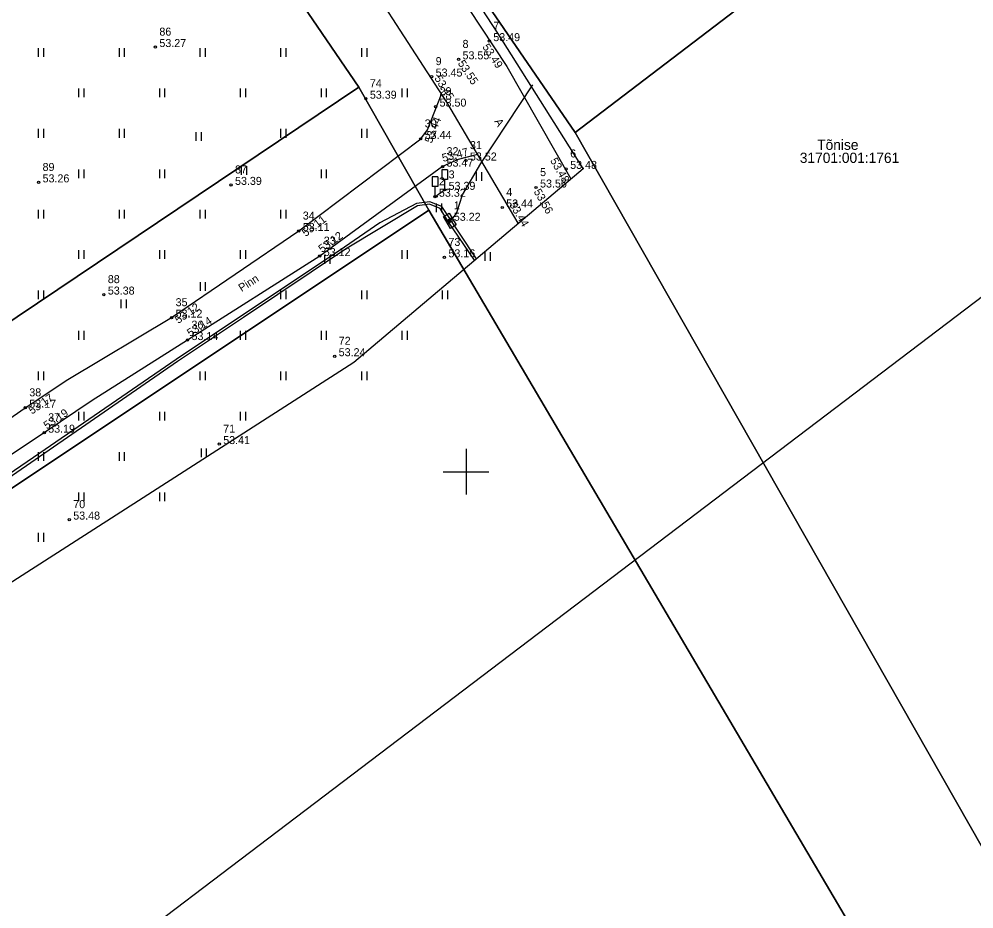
# Model space of a CAD drawing. Extents: x 538599 to 541973, y 6559689 to 6564516.
# Drawn here: x 540610.9 to 540694.4, y 6561211.7 to 6561289.6 of the extents above; entities that cross this region are included whole.
import ezdxf

# ---------------------------------------------------------------- set-up
doc = ezdxf.new("R2010")
doc.units = 0
for name, color, linetype in [('ELRAJATISMP', 7, 'Continuous'), ('HALJASTUS', 7, 'Continuous'), ('KORGUS-EH2000', 7, 'Continuous'), ('KPKAABEL', 7, 'Continuous'), ('LIIKLUS', 7, 'Continuous'), ('MOOTKORG-EH2000', 7, 'Continuous'), ('MOOTMPUNKT', 7, 'Continuous'), ('MOOTNR', 7, 'Continuous'), ('MOOTPIIR', 7, 'Continuous'), ('MPKAABEL', 7, 'Continuous'), ('PIIR', 7, 'Continuous'), ('TEE', 7, 'Continuous'), ('VORK', 7, 'Continuous'), ('VORMISTUS', 7, 'Continuous')]:
    doc.layers.add(name, color=color, linetype=linetype)

msp = doc.modelspace()

# ---------------------------------------------------------------- linework, layer by layer
at = {"layer": 'ELRAJATISMP'}
for p, q in [((540648.769, 6561272.238), (540648.255, 6561271.934)), ((540648.907, 6561272.004), (540648.393, 6561271.7))]:
    msp.add_line(p, q, dxfattribs=at)
msp.add_lwpolyline([(540648.534, 6561272.635), (540649.142, 6561271.607), (540648.628, 6561271.303), (540648.02, 6561272.331)], close=True, dxfattribs=at)
at = {"layer": 'HALJASTUS'}
for p, q in [((540612.567, 6561287.072), (540612.567, 6561286.31)), ((540613.022, 6561287.072), (540613.022, 6561286.31)), ((540619.638, 6561287.072), (540619.638, 6561286.31)), ((540620.093, 6561287.072), (540620.093, 6561286.31)), ((540626.709, 6561287.072), (540626.709, 6561286.31)), ((540627.164, 6561287.072), (540627.164, 6561286.31)), ((540633.78, 6561287.072), (540633.78, 6561286.31)), ((540634.235, 6561287.072), (540634.235, 6561286.31)), ((540640.851, 6561287.072), (540640.851, 6561286.31)), ((540641.307, 6561287.072), (540641.307, 6561286.31)), ((540616.103, 6561283.536), (540616.103, 6561282.775)), ((540616.558, 6561283.536), (540616.558, 6561282.775)), ((540623.174, 6561283.536), (540623.174, 6561282.775)), ((540623.629, 6561283.536), (540623.629, 6561282.775)), ((540630.245, 6561283.536), (540630.245, 6561282.775)), ((540630.7, 6561283.536), (540630.7, 6561282.775)), ((540637.316, 6561283.536), (540637.316, 6561282.775)), ((540637.771, 6561283.536), (540637.771, 6561282.775)), ((540644.387, 6561283.536), (540644.387, 6561282.775)), ((540644.842, 6561283.536), (540644.842, 6561282.775)), ((540612.567, 6561280), (540612.567, 6561279.239)), ((540613.022, 6561280), (540613.022, 6561279.239)), ((540619.638, 6561280), (540619.638, 6561279.239)), ((540620.093, 6561280), (540620.093, 6561279.239)), ((540626.363, 6561279.719), (540626.363, 6561278.958)), ((540626.818, 6561279.719), (540626.818, 6561278.958)), ((540633.78, 6561280), (540633.78, 6561279.239)), ((540634.235, 6561280), (540634.235, 6561279.239)), ((540640.851, 6561280), (540640.851, 6561279.239)), ((540641.307, 6561280), (540641.307, 6561279.239)), ((540616.103, 6561276.465), (540616.103, 6561275.704)), ((540616.558, 6561276.465), (540616.558, 6561275.704)), ((540623.174, 6561276.465), (540623.174, 6561275.704)), ((540623.629, 6561276.465), (540623.629, 6561275.704)), ((540630.328, 6561276.757), (540630.328, 6561275.996)), ((540630.783, 6561276.757), (540630.783, 6561275.996)), ((540637.316, 6561276.465), (540637.316, 6561275.704)), ((540637.771, 6561276.465), (540637.771, 6561275.704)), ((540650.899, 6561276.211), (540650.899, 6561275.45)), ((540651.354, 6561276.211), (540651.354, 6561275.45)), ((540647.4, 6561273.477), (540647.4, 6561272.716)), ((540647.855, 6561273.477), (540647.855, 6561272.716)), ((540612.567, 6561272.929), (540612.567, 6561272.168)), ((540613.022, 6561272.929), (540613.022, 6561272.168)), ((540619.638, 6561272.929), (540619.638, 6561272.168)), ((540620.093, 6561272.929), (540620.093, 6561272.168)), ((540626.709, 6561272.929), (540626.709, 6561272.168)), ((540627.164, 6561272.929), (540627.164, 6561272.168)), ((540633.78, 6561272.929), (540633.78, 6561272.168)), ((540634.235, 6561272.929), (540634.235, 6561272.168)), ((540616.103, 6561269.394), (540616.103, 6561268.633)), ((540616.558, 6561269.394), (540616.558, 6561268.633)), ((540623.174, 6561269.394), (540623.174, 6561268.633)), ((540623.629, 6561269.394), (540623.629, 6561268.633)), ((540630.245, 6561269.394), (540630.245, 6561268.633)), ((540630.7, 6561269.394), (540630.7, 6561268.633)), ((540637.627, 6561268.962), (540637.627, 6561268.201)), ((540638.082, 6561268.962), (540638.082, 6561268.201)), ((540644.387, 6561269.394), (540644.387, 6561268.633)), ((540644.842, 6561269.394), (540644.842, 6561268.633)), ((540651.644, 6561269.211), (540651.644, 6561268.45)), ((540652.099, 6561269.211), (540652.099, 6561268.45)), ((540626.726, 6561266.598), (540626.726, 6561265.837)), ((540627.181, 6561266.598), (540627.181, 6561265.837)), ((540612.567, 6561265.858), (540612.567, 6561265.097)), ((540613.022, 6561265.858), (540613.022, 6561265.097)), ((540633.78, 6561265.858), (540633.78, 6561265.097)), ((540634.235, 6561265.858), (540634.235, 6561265.097)), ((540640.851, 6561265.858), (540640.851, 6561265.097)), ((540641.307, 6561265.858), (540641.307, 6561265.097)), ((540647.923, 6561265.858), (540647.923, 6561265.097)), ((540648.378, 6561265.858), (540648.378, 6561265.097)), ((540619.805, 6561265.076), (540619.805, 6561264.315)), ((540620.26, 6561265.076), (540620.26, 6561264.315)), ((540616.103, 6561262.323), (540616.103, 6561261.562)), ((540616.558, 6561262.323), (540616.558, 6561261.562)), ((540630.245, 6561262.323), (540630.245, 6561261.562)), ((540630.7, 6561262.323), (540630.7, 6561261.562)), ((540637.316, 6561262.323), (540637.316, 6561261.562)), ((540637.771, 6561262.323), (540637.771, 6561261.562)), ((540644.387, 6561262.323), (540644.387, 6561261.562)), ((540644.842, 6561262.323), (540644.842, 6561261.562)), ((540612.567, 6561258.787), (540612.567, 6561258.026)), ((540613.022, 6561258.787), (540613.022, 6561258.026)), ((540626.709, 6561258.787), (540626.709, 6561258.026)), ((540627.164, 6561258.787), (540627.164, 6561258.026)), ((540633.78, 6561258.787), (540633.78, 6561258.026)), ((540634.235, 6561258.787), (540634.235, 6561258.026)), ((540640.851, 6561258.787), (540640.851, 6561258.026)), ((540641.307, 6561258.787), (540641.307, 6561258.026)), ((540616.103, 6561255.252), (540616.103, 6561254.491)), ((540616.558, 6561255.252), (540616.558, 6561254.491)), ((540623.174, 6561255.252), (540623.174, 6561254.491)), ((540623.629, 6561255.252), (540623.629, 6561254.491)), ((540630.245, 6561255.252), (540630.245, 6561254.491)), ((540630.7, 6561255.252), (540630.7, 6561254.491)), ((540612.567, 6561251.716), (540612.567, 6561250.955)), ((540613.022, 6561251.716), (540613.022, 6561250.955)), ((540619.638, 6561251.716), (540619.638, 6561250.955)), ((540620.093, 6561251.716), (540620.093, 6561250.955)), ((540626.82, 6561252.041), (540626.82, 6561251.28)), ((540627.275, 6561252.041), (540627.275, 6561251.28)), ((540616.103, 6561248.181), (540616.103, 6561247.42)), ((540616.558, 6561248.181), (540616.558, 6561247.42)), ((540623.174, 6561248.181), (540623.174, 6561247.42)), ((540623.629, 6561248.181), (540623.629, 6561247.42)), ((540612.567, 6561244.645), (540612.567, 6561243.884)), ((540613.022, 6561244.645), (540613.022, 6561243.884))]:
    msp.add_line(p, q, dxfattribs=at)
at = {"layer": 'KORGUS-EH2000'}
for centre in [(540622.82, 6561287.171), (540652.037, 6561287.689), (540649.345, 6561286.097), (540646.993, 6561284.59), (540641.235, 6561282.651), (540646.035, 6561279.138), (540647.947, 6561276.705), (540658.764, 6561276.507), (540612.599, 6561275.328), (540629.439, 6561275.108), (540656.13, 6561274.878), (540653.169, 6561273.131), (540635.368, 6561271.073), (540637.204, 6561268.881), (540648.112, 6561268.767), (540618.309, 6561265.51), (540624.24, 6561263.49), (540625.631, 6561261.527), (540638.509, 6561260.115), (540611.437, 6561255.604), (540613.091, 6561253.422), (540628.405, 6561252.425), (540615.285, 6561245.819)]:
    msp.add_circle(centre, 0.1, dxfattribs=at)
at = {"layer": 'KPKAABEL'}
msp.add_lwpolyline([(540650.91, 6561268.65), (540647.879, 6561273.223), (540646.82, 6561273.613), (540645.676, 6561273.469), (540642.461, 6561271.781), (540639.363, 6561269.658), (540624.625, 6561259.82), (540612.707, 6561251.641), (540589.754, 6561235.922)], dxfattribs=at)
at = {"layer": 'LIIKLUS'}
for p, q in [((540647.878, 6561276.425), (540647.878, 6561275.575)), ((540648.378, 6561276.425), (540647.878, 6561276.425)), ((540648.378, 6561276.425), (540648.378, 6561275.575)), ((540647.03, 6561275.82), (540647.03, 6561274.97)), ((540647.53, 6561275.82), (540647.03, 6561275.82)), ((540647.53, 6561275.82), (540647.53, 6561274.97)), ((540648.378, 6561275.575), (540647.878, 6561275.575)), ((540648.128, 6561275.575), (540648.128, 6561274.675)), ((540647.53, 6561274.97), (540647.03, 6561274.97)), ((540647.28, 6561274.97), (540647.28, 6561274.07)), ((540647.53, 6561274.07), (540647.28, 6561274.07)), ((540648.378, 6561274.675), (540648.128, 6561274.675))]:
    msp.add_line(p, q, dxfattribs=at)
msp.add_lwpolyline([(540647.28, 6561274.07), (540648.128, 6561274.675)], dxfattribs=at)
at = {"layer": 'MOOTMPUNKT'}
for centre in [(540622.82, 6561287.171), (540652.037, 6561287.689), (540649.345, 6561286.097), (540646.993, 6561284.59), (540641.235, 6561282.651), (540647.339, 6561281.959), (540646.035, 6561279.138), (540649.992, 6561277.241), (540647.947, 6561276.705), (540658.764, 6561276.507), (540612.599, 6561275.328), (540629.439, 6561275.108), (540648.128, 6561274.675), (540656.13, 6561274.878), (540647.28, 6561274.07), (540653.169, 6561273.131), (540648.581, 6561271.969), (540635.368, 6561271.073), (540637.204, 6561268.881), (540648.112, 6561268.767), (540618.309, 6561265.51), (540624.24, 6561263.49), (540625.631, 6561261.527), (540638.509, 6561260.115), (540611.437, 6561255.604), (540613.091, 6561253.422), (540628.405, 6561252.425), (540615.285, 6561245.819)]:
    msp.add_circle(centre, 0.1, dxfattribs=at)
at = {"layer": 'MOOTPIIR'}
msp.add_lwpolyline([(540582.869, 6561222.817), (540621.742, 6561247.747), (540640.195, 6561259.582), (540660.245, 6561276.551), (540652.795, 6561288.389), (540643.616, 6561302.458), (540615.416, 6561343.631), (540611.814, 6561347.628), (540600.551, 6561344.045)], dxfattribs=at)
at = {"layer": 'MPKAABEL'}
for points in [[(540648.449, 6561271.91), (540648.833, 6561272.204), (540649.157, 6561272.59), (540649.689, 6561274.252), (540651.306, 6561276.976), (540655.855, 6561283.862)], [(540650.747, 6561268.512), (540648.449, 6561271.91), (540647.738, 6561273.055), (540646.801, 6561273.41), (540645.746, 6561273.277), (540639.444, 6561269.471), (540630.539, 6561263.496), (540624.746, 6561259.652), (540607.46, 6561247.735)]]:
    msp.add_lwpolyline(points, dxfattribs=at)
at = {"layer": 'PIIR'}
for points in [[(540290.72, 6561746.68), (540427.24, 6561588.74), (540493.94, 6561511.13), (540543.58, 6561450.93), (540540.24, 6561448.03), (540578.89, 6561396.62), (540600.99, 6561365.08), (540659.54, 6561279.7), (540697.59, 6561212.89), (540728.6, 6561157.63), (540756.94, 6561107.21), (540762.6, 6561098.5), (540765.3, 6561101.59), (540815.83, 6561019.53), (540863.6, 6560935.22), (540880.61, 6560910.09), (540903.4, 6560875.14), (540927.11, 6560842.51), (540955.71, 6560805.99), (540982.2, 6560772.63), (541049.12, 6560693.03)], [(541045.65, 6560666.8), (540964.7, 6560765.19), (540868.94, 6560895.75), (540756.19, 6561084.56), (540744.95, 6561099.98), (540716.4, 6561150.76), (540687.02, 6561204.55), (540646.74, 6561272.89), (540640.63, 6561283.66), (540606.26, 6561333.96), (540569.6, 6561385.93), (540537.11, 6561431.06), (540500.82, 6561475.34), (540460.86, 6561522.64), (540423.13, 6561566.69), (540380.29, 6561616.49), (540342.1, 6561660.8)]]:
    msp.add_lwpolyline(points, dxfattribs=at)
for points in [[(540600.99, 6561365.08), (540701.8, 6561446.25), (540826.84, 6561548.44), (540828.67, 6561550.37), (540829.75, 6561549.48), (540833.57, 6561546.34), (540844.1, 6561537.92), (540853.65, 6561531.83), (540859.93, 6561522.78), (540863.38, 6561506.22), (540873.29, 6561464.28), (540881.92, 6561432.26), (540885.77, 6561408.65), (540892.47, 6561398.48), (540907.42, 6561381.68), (540938.49, 6561347.15), (540935.17, 6561343.58), (540808.31, 6561283.67), (540793.04, 6561301.15), (540771.58, 6561325.47), (540750.46, 6561349.5), (540705.14, 6561314.47), (540659.54, 6561279.7)], [(540491.21, 6561183.5), (540566.07, 6561233.36), (540528.84, 6561281.85), (540494.34, 6561324.62), (540458.27, 6561368.69), (540424.68, 6561408.57), (540384.55, 6561455.73), (540346.17, 6561499.11), (540330.12, 6561517.14), (540337.36, 6561523.32), (540348.28, 6561532.96), (540364.11, 6561514.94), (540353.14, 6561505.27), (540391.51, 6561461.86), (540431.74, 6561414.74), (540465.17, 6561374.89), (540501.31, 6561330.86), (540535.92, 6561287.97), (540573.77, 6561238.75), (540640.63, 6561283.66), (540646.74, 6561272.89), (540499, 6561174.36)], [(540535.92, 6561287.97), (540606.26, 6561333.96), (540640.63, 6561283.66), (540573.77, 6561238.75)], [(540659.54, 6561279.7), (540705.14, 6561314.47), (540727.47, 6561291.02), (540772.2, 6561324.85), (540793.34, 6561300.57), (540697.59, 6561212.89)], [(540490.55, 6561169.03), (540499, 6561174.36), (540646.74, 6561272.89), (540687.02, 6561204.55), (540544.29, 6561102.63)]]:
    msp.add_lwpolyline(points, close=True, dxfattribs=at)
at = {"layer": 'TEE'}
for points in [[(540611.142, 6561347.415), (540620.815, 6561333.355), (540632.508, 6561316.728), (540643.438, 6561300.807), (540653.575, 6561285.476), (540659.181, 6561275.65)], [(540654.57, 6561271.748), (540648.314, 6561282.335), (540638.501, 6561297.54), (540627.363, 6561313.661), (540616.232, 6561329.779), (540605.221, 6561345.531)], [(540599.72, 6561247.482), (540611.437, 6561255.604), (540615.167, 6561258.083), (540624.24, 6561263.49), (540635.368, 6561271.073), (540646.035, 6561279.138), (540646.628, 6561279.923), (540647.847, 6561283.058)], [(540651.018, 6561277.76), (540649.299, 6561277.32), (540647.947, 6561276.705), (540637.204, 6561268.881), (540625.631, 6561261.527), (540617.283, 6561256.229), (540613.091, 6561253.422), (540601.001, 6561245.406), (540588.333, 6561236.983), (540576.973, 6561229.557), (540565.171, 6561222.344), (540552.563, 6561213.52), (540540.165, 6561205.325), (540527.674, 6561197.002), (540515.613, 6561188.752), (540503.253, 6561180.454), (540486.571, 6561169.867)]]:
    msp.add_lwpolyline(points, dxfattribs=at)
at = {"layer": 'VORK'}
for p, q in [((540650, 6561252), (540650, 6561248)), ((540648, 6561250), (540652, 6561250))]:
    msp.add_line(p, q, dxfattribs=at)
at = {"layer": 'VORMISTUS'}
msp.add_lwpolyline([(540437.607, 6561637.113), (540710.791, 6561277.184), (540482.182, 6561103.671), (540208.998, 6561463.6)], close=True, dxfattribs=at)

# ---------------------------------------------------------------- texts
at = {"layer": 'KORGUS-EH2000'}
for s, p in [('53.27', (540623.17, 6561287.171)), ('53.39', (540641.585, 6561282.651)), ('53.26', (540612.949, 6561275.328)), ('53.39', (540629.789, 6561275.108)), ('53.16', (540648.462, 6561268.767)), ('53.38', (540618.659, 6561265.51)), ('53.24', (540638.859, 6561260.115)), ('53.41', (540628.755, 6561252.425)), ('53.48', (540615.635, 6561245.819))]:
    msp.add_text(s, height=0.7, dxfattribs=at).set_placement(p)
for s, rotation, p in [('53.49', 303.47305, (540651.4, 6561287.182)), ('53.55', 303.47305, (540649.249, 6561285.752)), ('53.45', 301.27202, (540647.208, 6561284.441)), ('53.44', 68.75248, (540646.993, 6561278.698)), ('53.47', 14.33803, (540647.993, 6561277.111)), ('53.48', 299.70676, (540657.336, 6561277.237)), ('53.56', 299.70676, (540655.9, 6561274.523)), ('53.44', 300.58055, (540653.762, 6561273.374)), ('53.11', 37.09184, (540635.968, 6561270.539)), ('53.12', 36.06541, (540637.398, 6561269.138)), ('53.12', 34.27186, (540624.821, 6561262.93)), ('53.14', 32.4337, (540625.866, 6561261.784)), ('53.17', 33.61451, (540612.012, 6561255.003)), ('53.19', 33.80429, (540613.326, 6561253.686))]:
    msp.add_text(s, height=0.7, rotation=rotation, dxfattribs=at).set_placement(p)
at = {"layer": 'MOOTKORG-EH2000'}
for s, p in [('53.49', (540652.387, 6561287.689)), ('53.27', (540623.17, 6561287.171)), ('53.55', (540649.695, 6561286.097)), ('53.45', (540647.343, 6561284.59)), ('53.39', (540641.585, 6561282.651)), ('53.50', (540647.689, 6561281.959)), ('53.44', (540646.385, 6561279.138)), ('53.47', (540648.297, 6561276.705)), ('53.52', (540650.342, 6561277.241)), ('53.48', (540659.114, 6561276.507)), ('53.26', (540612.949, 6561275.328)), ('53.39', (540629.789, 6561275.108)), ('53.56', (540656.48, 6561274.878)), ('53.32', (540647.63, 6561274.07)), ('53.39', (540648.478, 6561274.675)), ('53.44', (540653.519, 6561273.131)), ('53.22', (540648.931, 6561271.969)), ('53.11', (540635.718, 6561271.073)), ('53.12', (540637.554, 6561268.881)), ('53.16', (540648.462, 6561268.767)), ('53.38', (540618.659, 6561265.51)), ('53.12', (540624.59, 6561263.49)), ('53.14', (540625.981, 6561261.527)), ('53.24', (540638.859, 6561260.115)), ('53.17', (540611.787, 6561255.604)), ('53.19', (540613.441, 6561253.422)), ('53.41', (540628.755, 6561252.425)), ('53.48', (540615.635, 6561245.819))]:
    msp.add_text(s, height=0.7, dxfattribs=at).set_placement(p)
at = {"layer": 'MOOTNR'}
for s, p in [('7', (540652.387, 6561288.689)), ('86', (540623.17, 6561288.171)), ('8', (540649.695, 6561287.097)), ('9', (540647.343, 6561285.59)), ('74', (540641.585, 6561283.651)), ('29', (540647.689, 6561282.959)), ('30', (540646.385, 6561280.138)), ('31', (540650.342, 6561278.241)), ('32', (540648.297, 6561277.705)), ('6', (540659.114, 6561277.507)), ('89', (540612.949, 6561276.328)), ('87', (540629.789, 6561276.108)), ('3', (540648.478, 6561275.675)), ('5', (540656.48, 6561275.878)), ('2', (540647.63, 6561275.07)), ('4', (540653.519, 6561274.131)), ('1', (540648.931, 6561272.969)), ('34', (540635.718, 6561272.073)), ('33', (540637.554, 6561269.881)), ('73', (540648.462, 6561269.767)), ('88', (540618.659, 6561266.51)), ('35', (540624.59, 6561264.49)), ('36', (540625.981, 6561262.527)), ('72', (540638.859, 6561261.115)), ('38', (540611.787, 6561256.604)), ('37', (540613.441, 6561254.422)), ('71', (540628.755, 6561253.425)), ('70', (540615.635, 6561246.819))]:
    msp.add_text(s, height=0.7, dxfattribs=at).set_placement(p)
at = {"layer": 'PIIR'}
for s, p in [('Tõnise', (540680.727, 6561278.171)), ('31701:001:1761', (540679.204, 6561277.029))]:
    msp.add_text(s, height=0.9, rotation=0, dxfattribs=at).set_placement(p)
at = {"layer": 'TEE'}
for s, rotation, p in [('A', 300.58055, (540652.455, 6561280.665)), ('Pinn', 32.4337, (540630.364, 6561265.726))]:
    msp.add_text(s, height=0.7, rotation=rotation, dxfattribs=at).set_placement(p)

doc.saveas('drawing.dxf')
